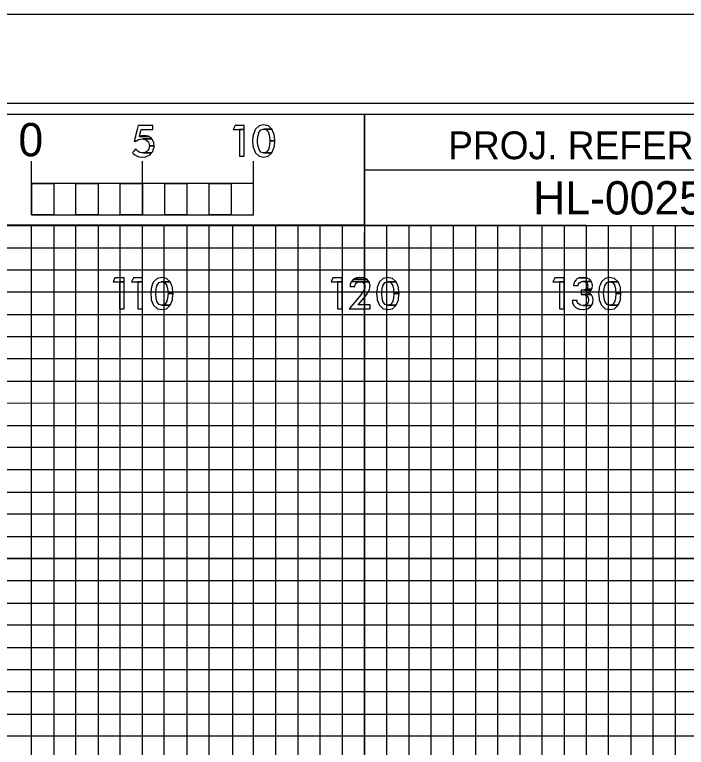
# Model space of a CAD drawing. Extents: x -13 to 323, y -5 to 1431.
# Drawn here: x 264.24 to 294.5, y 401.5 to 434.5 of the extents above; entities that cross this region are included whole.
import ezdxf

# ---------------------------------------------------------------- set-up
doc = ezdxf.new("R2010")
doc.units = 0
for name, color, linetype in [('Prop XS Bar Scale Labels', 7, 'Continuous'), ('Prop XS Offset Labels', 7, 'Continuous'), ('Prop XS Project Number', 7, 'Continuous'), ('Sheet Cross Section CELL', 7, 'Continuous'), ('Sheet Cross Section Grid Major CELL', 7, 'Continuous'), ('Sheet Cross Section Grid Middle CELL', 7, 'Continuous'), ('Sheet Cross Section Grid Minor 1 CELL', 7, 'Continuous'), ('Sheet Cross Section Grid Minor 2 CELL', 7, 'Continuous'), ('Sheet Cross Section Scale CELL', 7, 'Continuous'), ('Sheet Cutting Line CELL', 7, 'Continuous'), ('Sheet DOT Grid CELL', 7, 'Continuous'), ('Sheet Plot Border Inside CELL', 7, 'Continuous'), ('Sheet Plot Border Outside CELL', 7, 'Continuous')]:
    doc.layers.add(name, color=color, linetype=linetype)

msp = doc.modelspace()

# ---------------------------------------------------------------- linework, layer by layer
at = {"layer": 'Prop XS Bar Scale Labels'}
for points in [[(269.63, 428.81), (269.627, 428.798), (269.698, 428.798), (269.711, 428.81), (269.727, 428.824), (269.798, 428.867), (269.83, 428.877), (269.9, 428.899), (270.014, 428.905), (270.422, 428.905), (270.414, 428.92), (270.28, 429.015), (269.858, 429.015), (269.861, 429.028), (269.861, 429.028), (269.866, 429.048), (269.941, 429.326), (270.466, 429.326), (270.466, 429.511), (269.803, 429.511), (269.757, 429.326), (269.689, 429.048), (269.684, 429.028), (269.681, 429.015), (269.658, 428.92), (269.654, 428.905), (269.652, 428.899), (269.647, 428.877), (269.644, 428.867), (269.634, 428.824)], [(274.174, 429.511), (274.085, 429.329), (274.583, 429.329), (274.583, 429.511)], [(275.258, 428.125), (275.457, 428.084), (275.652, 428.125), (275.663, 428.127), (275.828, 428.279), (275.454, 428.279), (275.445, 428.281), (275.44, 428.283), (275.335, 428.312), (275.248, 428.425), (275.248, 428.426), (275.248, 428.426), (275.22, 428.527), (275.22, 428.529), (275.2, 428.602), (275.198, 428.606), (275.181, 428.809), (275.181, 428.811), (275.181, 428.813), (275.198, 429.015), (275.219, 429.092), (275.22, 429.094), (275.246, 429.192), (275.247, 429.195), (275.335, 429.31), (275.448, 429.339), (275.452, 429.34), (275.462, 429.343), (275.832, 429.343), (275.669, 429.492), (275.66, 429.494), (275.46, 429.538), (275.46, 429.538), (275.252, 429.494), (275.25, 429.492), (275.088, 429.343), (275.085, 429.34), (275.084, 429.339), (275.072, 429.31), (275.025, 429.195), (275.024, 429.192), (274.983, 429.094), (274.983, 429.092), (274.975, 429.015), (274.954, 428.813), (274.953, 428.811), (274.954, 428.809), (274.974, 428.606), (274.974, 428.602), (274.982, 428.529), (274.982, 428.527), (275.023, 428.426), (275.024, 428.425), (275.07, 428.312), (275.082, 428.283), (275.082, 428.281), (275.085, 428.279), (275.255, 428.127)], [(275.719, 429.015), (275.735, 428.813), (275.962, 428.813), (275.942, 429.015), (275.935, 429.092), (275.934, 429.094), (275.934, 429.094), (275.895, 429.192), (275.895, 429.192), (275.893, 429.195), (275.848, 429.31), (275.847, 429.31), (275.835, 429.339), (275.835, 429.34), (275.832, 429.343), (275.462, 429.343), (275.472, 429.34), (275.475, 429.339), (275.582, 429.31), (275.669, 429.195), (275.672, 429.192), (275.698, 429.094), (275.698, 429.092)], [(269.895, 429.028), (269.858, 429.015), (270.28, 429.015), (270.262, 429.028), (270.164, 429.048), (269.953, 429.048)], [(270.091, 429.062), (269.953, 429.048), (270.164, 429.048), (270.091, 429.062)], [(274.374, 429.329), (274.374, 428.12), (274.583, 428.12), (274.583, 429.329)], [(269.627, 428.798), (269.685, 428.786), (269.698, 428.798)], [(270.286, 428.711), (270.308, 428.591), (270.521, 428.591), (270.51, 428.711), (270.51, 428.711), (270.507, 428.751), (270.487, 428.786), (270.481, 428.798), (270.475, 428.81), (270.467, 428.824), (270.443, 428.867), (270.438, 428.877), (270.426, 428.899), (270.422, 428.905), (270.014, 428.905), (270.041, 428.899), (270.132, 428.877), (270.146, 428.867), (270.206, 428.824), (270.227, 428.81), (270.234, 428.798), (270.241, 428.786), (270.262, 428.751)], [(275.465, 428.281), (275.454, 428.279), (275.828, 428.279), (275.831, 428.281), (275.833, 428.283), (275.845, 428.312), (275.892, 428.425), (275.892, 428.426), (275.934, 428.527), (275.935, 428.529), (275.942, 428.602), (275.942, 428.606), (275.962, 428.809), (275.963, 428.811), (275.962, 428.813), (275.735, 428.813), (275.735, 428.811), (275.735, 428.809), (275.719, 428.606), (275.718, 428.602), (275.699, 428.529), (275.698, 428.527), (275.671, 428.426), (275.67, 428.425), (275.582, 428.312), (275.47, 428.283)], [(269.829, 428.103), (269.965, 428.084), (270.163, 428.103), (270.171, 428.107), (270.294, 428.167), (270.294, 428.167), (270.344, 428.191), (270.388, 428.245), (270.408, 428.269), (269.996, 428.269), (269.887, 428.288), (269.885, 428.289), (269.882, 428.29), (269.799, 428.336), (269.789, 428.347), (269.783, 428.353), (269.783, 428.353), (269.733, 428.405), (269.7, 428.455), (269.7, 428.455), (269.655, 428.405), (269.608, 428.353), (269.602, 428.347), (269.593, 428.336), (269.551, 428.29), (269.55, 428.289), (269.551, 428.288), (269.566, 428.269), (269.585, 428.245), (269.649, 428.191), (269.677, 428.167), (269.801, 428.107)], [(270.103, 428.288), (269.996, 428.269), (270.408, 428.269), (270.423, 428.288), (270.424, 428.289), (270.425, 428.29), (270.425, 428.29), (270.462, 428.336), (270.471, 428.347), (270.473, 428.353), (270.487, 428.405), (270.502, 428.46), (270.525, 428.544), (270.521, 428.591), (270.308, 428.591), (270.3, 428.544), (270.286, 428.46), (270.25, 428.405), (270.217, 428.353), (270.207, 428.347), (270.19, 428.336), (270.116, 428.29), (270.108, 428.289)]]:
    msp.add_lwpolyline(points, close=True, dxfattribs=at)
at = {"layer": 'Prop XS Offset Labels'}
for points in [[(268.76, 422.641), (268.671, 422.459), (269.17, 422.459), (269.17, 422.641)], [(268.961, 422.459), (268.961, 421.25), (269.17, 421.25), (269.17, 422.459)], [(269.587, 422.641), (269.498, 422.459), (269.997, 422.459), (269.997, 422.641)], [(269.788, 422.459), (269.788, 421.25), (269.997, 421.25), (269.997, 422.459)], [(270.672, 421.255), (270.871, 421.214), (271.066, 421.255), (271.077, 421.257), (271.242, 421.409), (270.868, 421.409), (270.858, 421.411), (270.853, 421.413), (270.749, 421.442), (270.662, 421.555), (270.661, 421.556), (270.661, 421.556), (270.634, 421.657), (270.633, 421.659), (270.613, 421.732), (270.612, 421.736), (270.594, 421.939), (270.594, 421.941), (270.595, 421.943), (270.612, 422.145), (270.633, 422.222), (270.633, 422.224), (270.66, 422.322), (270.661, 422.325), (270.749, 422.44), (270.862, 422.469), (270.865, 422.47), (270.876, 422.473), (271.246, 422.473), (271.082, 422.622), (271.074, 422.624), (270.873, 422.668), (270.873, 422.668), (270.665, 422.624), (270.663, 422.622), (270.502, 422.473), (270.499, 422.47), (270.498, 422.469), (270.486, 422.44), (270.439, 422.325), (270.437, 422.322), (270.397, 422.224), (270.397, 422.222), (270.389, 422.145), (270.367, 421.943), (270.367, 421.941), (270.367, 421.939), (270.387, 421.736), (270.388, 421.732), (270.395, 421.659), (270.396, 421.657), (270.437, 421.556), (270.437, 421.555), (270.483, 421.442), (270.495, 421.413), (270.496, 421.411), (270.499, 421.409), (270.669, 421.257)], [(271.132, 422.145), (271.149, 421.943), (271.376, 421.943), (271.356, 422.145), (271.349, 422.222), (271.348, 422.224), (271.348, 422.224), (271.308, 422.322), (271.308, 422.322), (271.307, 422.325), (271.261, 422.44), (271.261, 422.44), (271.249, 422.469), (271.249, 422.47), (271.246, 422.473), (270.876, 422.473), (270.885, 422.47), (270.889, 422.469), (270.995, 422.44), (271.083, 422.325), (271.085, 422.322), (271.111, 422.224), (271.112, 422.222)], [(278.581, 422.641), (278.492, 422.459), (278.99, 422.459), (278.99, 422.641)], [(278.781, 422.459), (278.781, 421.25), (278.99, 421.25), (278.99, 422.459)], [(279.465, 421.432), (279.313, 421.25), (280.253, 421.25), (280.253, 421.432), (279.719, 421.432), (279.898, 421.638), (280.095, 421.879), (280.097, 421.881), (280.208, 422.069), (280.208, 422.069), (280.211, 422.074), (280.235, 422.193), (280.247, 422.254), (280.252, 422.279), (280.25, 422.29), (280.249, 422.293), (280.236, 422.354), (280.235, 422.36), (280.233, 422.37), (280.222, 422.421), (280.222, 422.421), (280.219, 422.435), (280.213, 422.461), (280.211, 422.464), (280.207, 422.468), (279.839, 422.468), (279.85, 422.464), (279.858, 422.461), (279.933, 422.435), (279.946, 422.421), (279.996, 422.37), (280, 422.36), (280.002, 422.354), (280.022, 422.293), (280.022, 422.29), (280.022, 422.279), (280.022, 422.254), (280.021, 422.193), (279.973, 422.074), (279.972, 422.069), (279.839, 421.881), (279.838, 421.879), (279.637, 421.638)], [(279.349, 422.279), (279.347, 422.254), (279.567, 422.254), (279.569, 422.279), (279.57, 422.29), (279.571, 422.293), (279.593, 422.354), (279.598, 422.36), (279.606, 422.37), (279.645, 422.421), (279.673, 422.435), (279.725, 422.461), (279.73, 422.464), (279.839, 422.468), (280.207, 422.468), (280.197, 422.479), (279.41, 422.479), (279.405, 422.468), (279.403, 422.464), (279.402, 422.461), (279.39, 422.435), (279.384, 422.421), (279.361, 422.37), (279.357, 422.36), (279.356, 422.354), (279.35, 422.293), (279.35, 422.29)], [(279.507, 422.583), (279.41, 422.479), (280.197, 422.479), (280.108, 422.583)], [(279.512, 422.585), (279.507, 422.583), (280.108, 422.583), (280.106, 422.585), (279.974, 422.645), (279.958, 422.652), (279.794, 422.668), (279.794, 422.668), (279.685, 422.652), (279.637, 422.645)], [(280.851, 421.255), (281.051, 421.214), (281.245, 421.255), (281.256, 421.257), (281.422, 421.409), (281.048, 421.409), (281.038, 421.411), (281.033, 421.413), (280.928, 421.442), (280.841, 421.555), (280.841, 421.556), (280.841, 421.556), (280.813, 421.657), (280.813, 421.659), (280.793, 421.732), (280.792, 421.736), (280.774, 421.939), (280.774, 421.941), (280.774, 421.943), (280.792, 422.145), (280.812, 422.222), (280.813, 422.224), (280.839, 422.322), (280.84, 422.325), (280.928, 422.44), (281.041, 422.469), (281.045, 422.47), (281.055, 422.473), (281.425, 422.473), (281.262, 422.622), (281.254, 422.624), (281.053, 422.668), (281.053, 422.668), (280.845, 422.624), (280.843, 422.622), (280.681, 422.473), (280.678, 422.47), (280.678, 422.469), (280.665, 422.44), (280.618, 422.325), (280.617, 422.322), (280.577, 422.224), (280.576, 422.222), (280.568, 422.145), (280.547, 421.943), (280.547, 421.941), (280.547, 421.939), (280.567, 421.736), (280.567, 421.732), (280.575, 421.659), (280.575, 421.657), (280.616, 421.556), (280.617, 421.555), (280.663, 421.442), (280.675, 421.413), (280.676, 421.411), (280.679, 421.409), (280.848, 421.257)], [(281.312, 422.145), (281.328, 421.943), (281.555, 421.943), (281.536, 422.145), (281.528, 422.222), (281.528, 422.224), (281.527, 422.224), (281.488, 422.322), (281.488, 422.322), (281.487, 422.325), (281.441, 422.44), (281.44, 422.44), (281.429, 422.469), (281.428, 422.47), (281.425, 422.473), (281.055, 422.473), (281.065, 422.47), (281.068, 422.469), (281.175, 422.44), (281.262, 422.325), (281.265, 422.322), (281.291, 422.224), (281.291, 422.222)], [(288.581, 422.641), (288.492, 422.459), (288.99, 422.459), (288.99, 422.641)], [(288.781, 422.459), (288.781, 421.25), (288.99, 421.25), (288.99, 422.459)], [(289.42, 422.315), (289.418, 422.297), (289.626, 422.297), (289.627, 422.315), (289.639, 422.365), (289.64, 422.372), (289.641, 422.373), (289.683, 422.433), (289.688, 422.436), (289.696, 422.44), (289.748, 422.47), (289.785, 422.476), (289.795, 422.478), (289.835, 422.485), (290.217, 422.485), (290.165, 422.561), (290.129, 422.582), (290.128, 422.582), (290.022, 422.644), (289.982, 422.65), (289.69, 422.65), (289.678, 422.644), (289.553, 422.582), (289.536, 422.561), (289.471, 422.485), (289.466, 422.478), (289.465, 422.476), (289.463, 422.47), (289.452, 422.44), (289.45, 422.436), (289.449, 422.433), (289.428, 422.373), (289.427, 422.372), (289.425, 422.365)], [(289.853, 422.668), (289.69, 422.65), (289.982, 422.65)], [(290.007, 422.155), (289.988, 422.131), (290.23, 422.131), (290.246, 422.155), (290.254, 422.201), (290.271, 422.289), (290.272, 422.295), (290.272, 422.297), (290.269, 422.315), (290.26, 422.365), (290.259, 422.372), (290.259, 422.373), (290.259, 422.373), (290.249, 422.433), (290.248, 422.436), (290.248, 422.44), (290.227, 422.47), (290.223, 422.476), (290.222, 422.478), (290.217, 422.485), (289.835, 422.485), (289.901, 422.478), (289.919, 422.476), (289.931, 422.47), (289.986, 422.44), (289.995, 422.436), (289.997, 422.433), (290.04, 422.373), (290.04, 422.372), (290.042, 422.365), (290.051, 422.315), (290.054, 422.297), (290.055, 422.295), (290.056, 422.289), (290.041, 422.201)], [(290.851, 421.255), (291.051, 421.214), (291.245, 421.255), (291.256, 421.257), (291.422, 421.409), (291.048, 421.409), (291.038, 421.411), (291.033, 421.413), (290.928, 421.442), (290.841, 421.555), (290.841, 421.556), (290.841, 421.556), (290.813, 421.657), (290.813, 421.659), (290.793, 421.732), (290.792, 421.736), (290.774, 421.939), (290.774, 421.941), (290.774, 421.943), (290.792, 422.145), (290.812, 422.222), (290.813, 422.224), (290.839, 422.322), (290.84, 422.325), (290.928, 422.44), (291.041, 422.469), (291.045, 422.47), (291.055, 422.473), (291.425, 422.473), (291.262, 422.622), (291.254, 422.624), (291.053, 422.668), (291.053, 422.668), (290.845, 422.624), (290.843, 422.622), (290.681, 422.473), (290.678, 422.47), (290.678, 422.469), (290.665, 422.44), (290.618, 422.325), (290.617, 422.322), (290.577, 422.224), (290.576, 422.222), (290.568, 422.145), (290.547, 421.943), (290.547, 421.941), (290.547, 421.939), (290.567, 421.736), (290.567, 421.732), (290.575, 421.659), (290.575, 421.657), (290.616, 421.556), (290.617, 421.555), (290.663, 421.442), (290.675, 421.413), (290.676, 421.411), (290.679, 421.409), (290.848, 421.257)], [(291.312, 422.145), (291.328, 421.943), (291.555, 421.943), (291.536, 422.145), (291.528, 422.222), (291.528, 422.224), (291.527, 422.224), (291.488, 422.322), (291.488, 422.322), (291.487, 422.325), (291.441, 422.44), (291.44, 422.44), (291.429, 422.469), (291.428, 422.47), (291.425, 422.473), (291.055, 422.473), (291.065, 422.47), (291.068, 422.469), (291.175, 422.44), (291.262, 422.325), (291.265, 422.322), (291.291, 422.224), (291.291, 422.222)], [(289.765, 421.956), (289.765, 421.9), (290.194, 421.9), (290.119, 421.956), (290.029, 421.983), (290.095, 422), (290.181, 422.053), (290.2, 422.084), (290.201, 422.085), (290.207, 422.095), (289.915, 422.095), (289.83, 422.085), (289.765, 422.084), (289.765, 422.053), (289.765, 422), (289.765, 421.983)], [(289.988, 422.131), (289.915, 422.095), (290.207, 422.095), (290.23, 422.131)], [(270.878, 421.411), (270.868, 421.409), (271.242, 421.409), (271.245, 421.411), (271.247, 421.413), (271.259, 421.442), (271.305, 421.555), (271.306, 421.556), (271.348, 421.657), (271.348, 421.659), (271.355, 421.732), (271.356, 421.736), (271.376, 421.939), (271.376, 421.941), (271.376, 421.943), (271.149, 421.943), (271.149, 421.941), (271.148, 421.939), (271.132, 421.736), (271.132, 421.732), (271.112, 421.659), (271.112, 421.657), (271.085, 421.556), (271.084, 421.555), (270.995, 421.442), (270.883, 421.413)], [(281.058, 421.411), (281.048, 421.409), (281.422, 421.409), (281.425, 421.411), (281.426, 421.413), (281.438, 421.442), (281.485, 421.555), (281.485, 421.556), (281.527, 421.657), (281.528, 421.659), (281.535, 421.732), (281.535, 421.736), (281.555, 421.939), (281.556, 421.941), (281.555, 421.943), (281.328, 421.943), (281.328, 421.941), (281.328, 421.939), (281.312, 421.736), (281.312, 421.732), (281.292, 421.659), (281.291, 421.657), (281.264, 421.556), (281.263, 421.555), (281.175, 421.442), (281.063, 421.413)], [(289.925, 421.416), (289.849, 421.401), (290.229, 421.401), (290.239, 421.416), (290.243, 421.423), (290.243, 421.423), (290.275, 421.471), (290.277, 421.479), (290.277, 421.482), (290.283, 421.516), (290.292, 421.562), (290.293, 421.567), (290.303, 421.62), (290.297, 421.662), (290.285, 421.751), (290.283, 421.763), (290.25, 421.826), (290.223, 421.877), (290.222, 421.88), (290.197, 421.898), (290.194, 421.9), (289.81, 421.9), (289.877, 421.898), (289.951, 421.88), (289.963, 421.877), (290.033, 421.826), (290.07, 421.763), (290.077, 421.751), (290.092, 421.662), (290.088, 421.62), (290.082, 421.567), (290.08, 421.562), (290.057, 421.516), (290.039, 421.482), (290.035, 421.479), (290.025, 421.471), (289.957, 421.423)], [(291.058, 421.411), (291.048, 421.409), (291.422, 421.409), (291.425, 421.411), (291.426, 421.413), (291.438, 421.442), (291.485, 421.555), (291.485, 421.556), (291.527, 421.657), (291.528, 421.659), (291.535, 421.732), (291.535, 421.736), (291.555, 421.939), (291.556, 421.941), (291.555, 421.943), (291.328, 421.943), (291.328, 421.941), (291.328, 421.939), (291.312, 421.736), (291.312, 421.732), (291.292, 421.659), (291.291, 421.657), (291.264, 421.556), (291.263, 421.555), (291.175, 421.442), (291.063, 421.413)], [(289.677, 421.229), (289.854, 421.214), (289.936, 421.229), (290.042, 421.248), (290.123, 421.297), (290.187, 421.336), (290.228, 421.399), (290.229, 421.401), (289.849, 421.401), (289.72, 421.416), (289.711, 421.423), (289.639, 421.471), (289.628, 421.479), (289.626, 421.482), (289.608, 421.516), (289.584, 421.562), (289.584, 421.567), (289.58, 421.62), (289.58, 421.625), (289.361, 421.625), (289.362, 421.62), (289.369, 421.567), (289.37, 421.562), (289.377, 421.516), (289.391, 421.482), (289.392, 421.479), (289.395, 421.471), (289.415, 421.423), (289.418, 421.416), (289.425, 421.401), (289.426, 421.399), (289.49, 421.336), (289.53, 421.297), (289.635, 421.248)]]:
    msp.add_lwpolyline(points, close=True, dxfattribs=at)
at = {"layer": 'Sheet Cross Section CELL'}
for p, q in [((280, 427.5), (280, 425)), ((320, 427.49), (280, 427.49)), ((280, 425), (320, 425))]:
    msp.add_line(p, q, dxfattribs=at)
for points in [[(320, 430), (0, 430), (0, 220), (320, 220)], [(280, 430), (260, 430), (260, 425.03), (280, 425.03)], [(320, 430), (280, 430), (280, 425), (320, 425)]]:
    msp.add_lwpolyline(points, close=True, dxfattribs=at)
at = {"layer": 'Sheet Cross Section Grid Major CELL'}
for p, q in [((270, 220), (270, 425)), ((290, 425), (280, 425)), ((280, 425), (280, 220)), ((290, 220), (290, 425))]:
    msp.add_line(p, q, dxfattribs=at)
msp.add_lwpolyline([(0, 420), (320, 420), (320, 410), (0, 410)], dxfattribs=at)
at = {"layer": 'Sheet Cross Section Grid Middle CELL'}
for points in [[(255, 220), (255, 430), (259.93, 430), (260, 430), (260, 425), (264.99, 425), (264.99, 220)], [(0, 425), (275, 425)], [(275, 220), (275, 425), (285, 425), (285, 220)], [(0, 405), (320, 405), (320, 415), (0, 415)]]:
    msp.add_lwpolyline(points, dxfattribs=at)
at = {"layer": 'Sheet Cross Section Grid Minor 1 CELL'}
msp.add_line((0, 424), (320, 424), dxfattribs=at)
for points in [[(0, 423), (270, 423), (320, 423), (320, 422), (0, 422)], [(0, 421), (320, 421), (320, 419), (0, 419)], [(0, 418), (320, 418), (320, 417), (0, 416.98)], [(0, 416), (320, 416), (320, 414), (0, 414)], [(0, 413), (320, 413), (320, 412), (0, 412)], [(0, 411), (320, 411), (320, 409), (0, 409)], [(0, 408), (320, 408), (320, 407), (0, 407)], [(0, 406), (320, 406), (320, 404), (0, 404)], [(0, 403), (320, 403), (320, 402), (0, 402)]]:
    msp.add_lwpolyline(points, dxfattribs=at)
at = {"layer": 'Sheet Cross Section Grid Minor 2 CELL'}
for p, q in [((267, 425), (266.01, 425)), ((266.01, 425), (266.01, 220)), ((267, 220), (267, 425)), ((269, 425), (268, 425)), ((268, 425), (268, 220)), ((269, 220), (269, 425))]:
    msp.add_line(p, q, dxfattribs=at)
for points in [[(270, 220), (270.98, 220), (270.98, 425), (272, 425), (272, 220)], [(272, 220), (273, 220), (273, 425), (274.05, 425), (274.05, 220)], [(275, 220), (276, 220), (276, 425), (277, 425), (277, 220)], [(277, 220), (278, 220), (278, 425), (279, 425), (279, 220)], [(280, 220), (281, 220), (281, 425), (282, 425), (282, 220)], [(282, 220), (283, 220), (283, 425), (284, 425), (284, 220)], [(285, 220), (286, 220), (286, 425), (287, 425), (287, 220)], [(287, 220), (288, 220), (288, 425), (289, 425), (289, 220)], [(290, 220), (291, 220), (291, 425), (292, 425), (292, 220)], [(292, 220), (293, 220), (293, 425), (294, 425), (294, 220)]]:
    msp.add_lwpolyline(points, dxfattribs=at)
at = {"layer": 'Sheet Cross Section Scale CELL'}
for p, q in [((265, 425.49), (265, 427.9)), ((265, 426.9), (265, 427.9)), ((270, 425.49), (270, 427.9)), ((275, 425.49), (275, 427.9)), ((275, 426.9), (275, 427.9))]:
    msp.add_line(p, q, dxfattribs=at)
for points in [[(275, 426.9), (265, 426.9), (265, 425.49), (275, 425.49)], [(265, 426.9), (266, 426.9), (266, 425.49), (265, 425.49)], [(267, 426.9), (268, 426.9), (268, 425.49), (267, 425.49)], [(269, 426.9), (270, 426.9), (270, 425.49), (269, 425.49)], [(271, 426.9), (272, 426.9), (272, 425.49), (271, 425.49)], [(273, 426.9), (274, 426.9), (274, 425.49), (273, 425.49)]]:
    msp.add_lwpolyline(points, close=True, dxfattribs=at)
at = {"layer": 'Sheet Cutting Line CELL'}
msp.add_line((323.3, 434.5), (-13.4, 434.5), dxfattribs=at)
at = {"layer": 'Sheet DOT Grid CELL'}
for p, q in [((270, 220), (270, 424.687)), ((280, 220), (280, 424.687)), ((290, 220), (290, 424.687)), ((0, 420), (320, 420)), ((0, 410), (320, 410))]:
    msp.add_line(p, q, dxfattribs=at)
at = {"layer": 'Sheet Plot Border Inside CELL'}
msp.add_lwpolyline([(-10.8, 219.5), (322.4, 219.5), (322.4, 430.5), (-10.8, 430.5)], close=True, dxfattribs=at)
at = {"layer": 'Sheet Plot Border Outside CELL'}
msp.add_lwpolyline([(-13.4, 215.5), (323.3, 215.5), (323.3, 434.5), (-13.4, 434.5)], close=True, dxfattribs=at)

# ---------------------------------------------------------------- texts
at = {"layer": 'Prop XS Project Number'}
msp.add_text('HL-0025', height=1.5, dxfattribs=at).set_placement((287.598, 425.5))
at = {"layer": 'Sheet Cross Section CELL'}
msp.add_text('PROJ. REFERENCE NO.', height=1.24998, dxfattribs=at).set_placement((283.77, 427.99))
at = {"layer": 'Sheet Cross Section Scale CELL'}
msp.add_text('0', height=1.5, dxfattribs=at).set_placement((264.41, 428.12))

doc.saveas('drawing.dxf')
